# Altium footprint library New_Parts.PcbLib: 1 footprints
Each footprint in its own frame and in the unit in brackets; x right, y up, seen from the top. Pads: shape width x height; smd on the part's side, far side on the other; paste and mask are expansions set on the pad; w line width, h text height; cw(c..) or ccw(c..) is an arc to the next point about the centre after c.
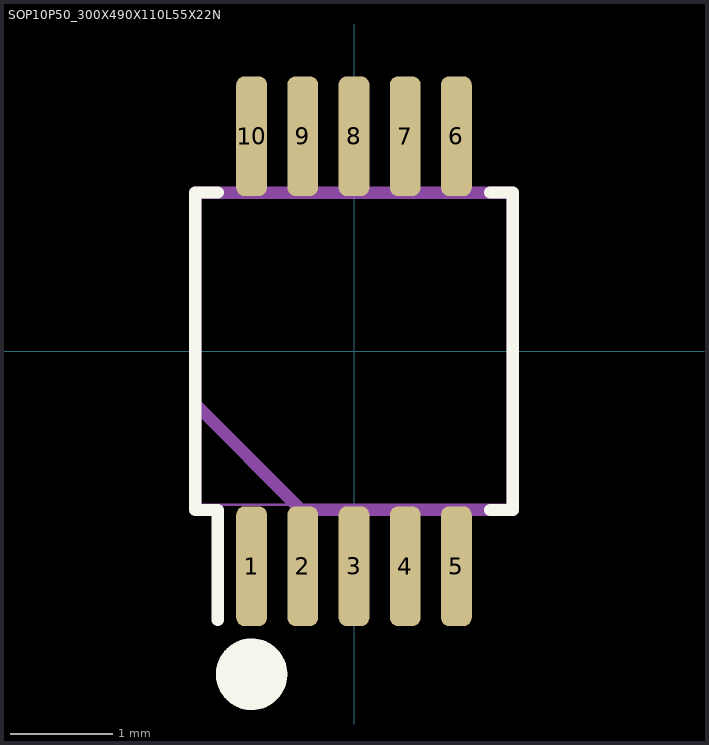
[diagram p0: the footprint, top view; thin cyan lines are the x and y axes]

## SOP10P50_300X490X110L55X22N [mm]
height 1.1
pads (10):
  rrect53% 0.3x1.17 smd: 1(-1,-2.1) 2(-0.5,-2.1) 3(0,-2.1) 4(0.5,-2.1) 5(1,-2.1) 6(1,2.1) 7(0.5,2.1) 8(0,2.1) 9(-0.5,2.1) 10(-1,2.1)
Top Overlay:
  circle w0.35: c-1,-3.155 r0.175
  lines w0.12: -1.33,-2.625 -1.33,-1.55 -1.55,-1.55 -1.55,1.55 -1.33,1.55 ; 1.33,-1.55 1.55,-1.55 1.55,1.55 1.33,1.55
Top Solder:
  circle w0.05: c0,0 r0.25
  lines w0.05: -0.35,0 0.35,0 ; 0,-0.35 0,0.35 ; -1.75,-1.75 -1.75,1.75 -1.35,1.75 -1.35,2.885 1.35,2.885 1.35,1.75 1.75,1.75 1.75,-1.75 1.35,-1.75 1.35,-2.885 -1.35,-2.885 -1.35,-1.75 -1.75,-1.75
Assembly Top:
  lines w0.12: -1.55,-0.517 -0.517,-1.55 1.55,-1.55 1.55,1.55 -1.55,1.55 -1.55,-0.517
3D Top:
  lines w0.025: -1.5,-1.5 -1.5,1.5 1.5,1.5 1.5,-1.5 -1.5,-1.5 ; -1.11,-2.45 -0.89,-2.45 -0.89,-1.9 -1.11,-1.9 -1.11,-2.45 ; -1.11,1.9 -0.89,1.9 -0.89,2.45 -1.11,2.45 -1.11,1.9 ; -0.61,-2.45 -0.39,-2.45 -0.39,-1.9 -0.61,-1.9 -0.61,-2.45 ; -0.61,1.9 -0.39,1.9 -0.39,2.45 -0.61,2.45 -0.61,1.9 ; -0.11,-2.45 0.11,-2.45 0.11,-1.9 -0.11,-1.9 -0.11,-2.45 ; -0.11,1.9 0.11,1.9 0.11,2.45 -0.11,2.45 -0.11,1.9 ; 0.39,-2.45 0.61,-2.45 0.61,-1.9 0.39,-1.9 0.39,-2.45 ; 0.39,1.9 0.61,1.9 0.61,2.45 0.39,2.45 0.39,1.9 ; 0.89,-2.45 1.11,-2.45 1.11,-1.9 0.89,-1.9 0.89,-2.45 ; 0.89,1.9 1.11,1.9 1.11,2.45 0.89,2.45 0.89,1.9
